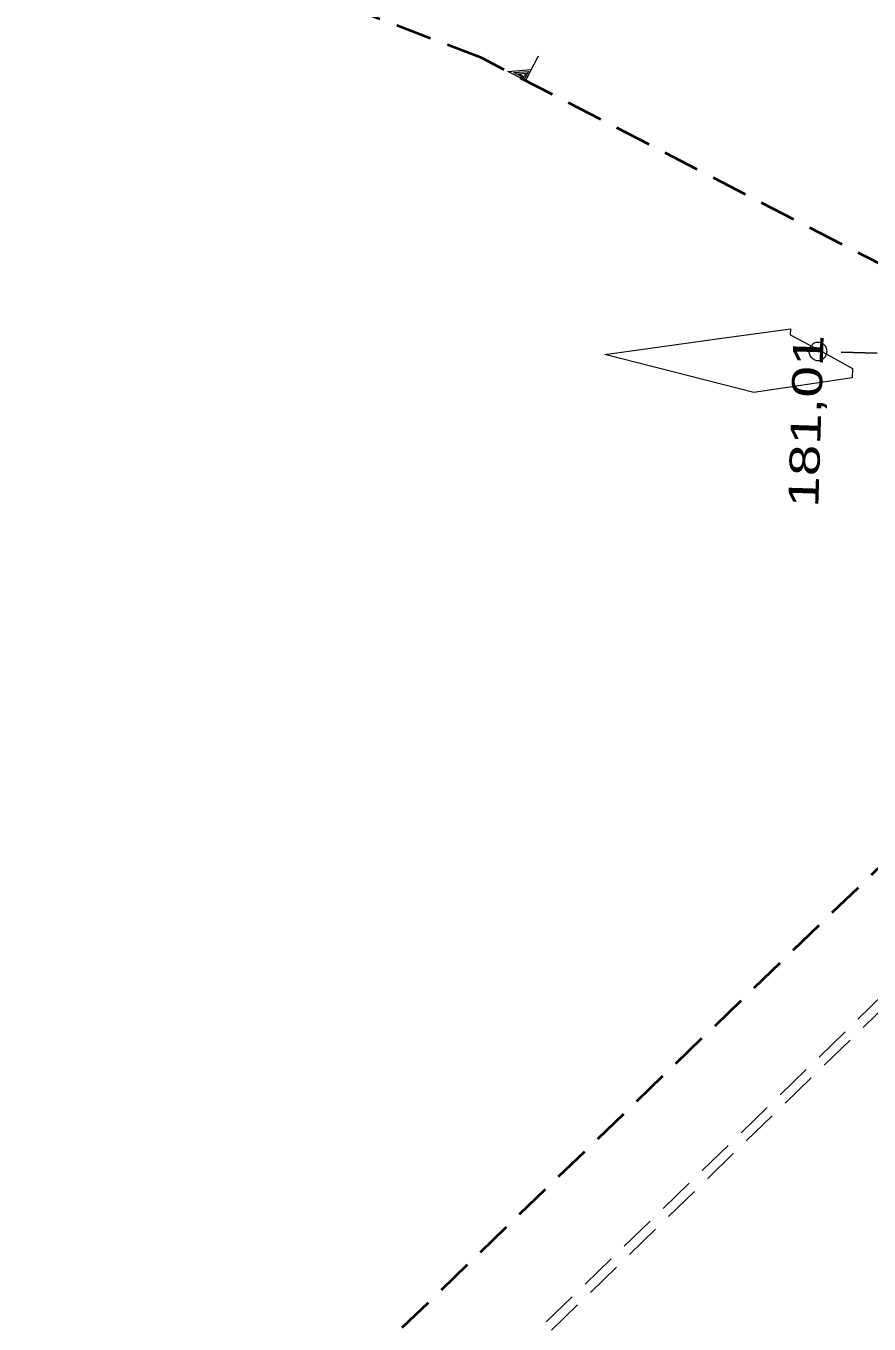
# Model space of a CAD drawing. Extents: x -740851 to -738888, y -1041382 to -1040235.
# Drawn here: x -739839.61 to -739811.68, y -1040534.07 to -1040491.06 of the extents above; entities that cross this region are included whole.
import ezdxf

# ---------------------------------------------------------------- set-up
doc = ezdxf.new("R2010")
doc.units = 0
doc.header["$LTSCALE"] = 0.4
doc.linetypes.add('MEDIUM_DASHED', pattern=[4.5, 3, -1.5])
for name, color, linetype, lineweight in [('18', 7, 'Continuous', 13), ('38', 7, 'Continuous', 13), ('39', 7, 'MEDIUM_DASHED', 13), ('8', 7, 'Continuous', 13)]:
    doc.layers.add(name, color=color, linetype=linetype, lineweight=lineweight)

msp = doc.modelspace()

# ---------------------------------------------------------------- linework, layer by layer
at = {"layer": '18', "linetype": 'MEDIUM_DASHED', "lineweight": 40}
msp.add_lwpolyline([(-739801.38, -1040504.08), (-739824.522, -1040492.113), (-739843.173, -1040485.007), (-739862.094, -1040478.655), (-739868.01, -1040476.84)], dxfattribs=at)
at = {"layer": '18'}
for points in [[(-739822.642, -1040492.053), (-739823.062, -1040492.865), (-739823.642, -1040492.566), (-739822.873, -1040492.499)], [(-739822.958, -1040492.558), (-739823.08, -1040492.795), (-739823.45, -1040492.603), (-739822.954, -1040492.56)], [(-739823.044, -1040492.621), (-739823.106, -1040492.74), (-739823.296, -1040492.642), (-739823.041, -1040492.624)]]:
    msp.add_lwpolyline(points, dxfattribs=at)
for points in [[(-739814.28, -1040501.09), (-739814.29, -1040501.29), (-739813.225, -1040501.849), (-739812.226, -1040502.402), (-739812.24, -1040502.71), (-739815.5, -1040503.2), (-739820.432, -1040501.939), (-739816.636, -1040501.415)], [(-739813.666, -1040501.883), (-739813.661, -1040501.913), (-739813.651, -1040501.942), (-739813.641, -1040501.97), (-739813.625, -1040501.998), (-739813.603, -1040502.025), (-739813.581, -1040502.046), (-739813.56, -1040502.067), (-739813.533, -1040502.087), (-739813.507, -1040502.102), (-739813.481, -1040502.116), (-739813.448, -1040502.129), (-739813.417, -1040502.137), (-739813.387, -1040502.138), (-739813.356, -1040502.14), (-739813.327, -1040502.136), (-739813.297, -1040502.131), (-739813.268, -1040502.121), (-739813.24, -1040502.111), (-739813.212, -1040502.095), (-739813.185, -1040502.073), (-739813.164, -1040502.051), (-739813.143, -1040502.03), (-739813.123, -1040502.003), (-739813.108, -1040501.977), (-739813.094, -1040501.951), (-739813.081, -1040501.918), (-739813.073, -1040501.887), (-739813.072, -1040501.857), (-739813.07, -1040501.826), (-739813.074, -1040501.797), (-739813.079, -1040501.767), (-739813.089, -1040501.738), (-739813.099, -1040501.71), (-739813.115, -1040501.682), (-739813.137, -1040501.655), (-739813.159, -1040501.634), (-739813.18, -1040501.613), (-739813.207, -1040501.593), (-739813.233, -1040501.578), (-739813.259, -1040501.564), (-739813.292, -1040501.551), (-739813.323, -1040501.543), (-739813.353, -1040501.542), (-739813.384, -1040501.54), (-739813.413, -1040501.544), (-739813.443, -1040501.549), (-739813.472, -1040501.559), (-739813.5, -1040501.569), (-739813.528, -1040501.585), (-739813.555, -1040501.607), (-739813.576, -1040501.629), (-739813.597, -1040501.65), (-739813.617, -1040501.677), (-739813.632, -1040501.703), (-739813.646, -1040501.729), (-739813.659, -1040501.762), (-739813.667, -1040501.793), (-739813.668, -1040501.823), (-739813.67, -1040501.854)]]:
    msp.add_lwpolyline(points, close=True, dxfattribs=at)
at = {"layer": '18', "linetype": 'MEDIUM_DASHED', "lineweight": 25}
msp.add_lwpolyline([(-739764.8, -1040509.34), (-739769.103, -1040507.543), (-739773.123, -1040506.414), (-739777.515, -1040505.303), (-739782.543, -1040504.403), (-739786.933, -1040503.786), (-739791.776, -1040503.067), (-739793.941, -1040502.746), (-739796.322, -1040502.462), (-739800.245, -1040502.273), (-739807.808, -1040502.015), (-739813.37, -1040501.84)], dxfattribs=at)
at = {"layer": '38', "linetype": 'MEDIUM_DASHED'}
msp.add_lwpolyline([(-739768.78, -1040522.16), (-739769.767, -1040523.416), (-739770.8, -1040525.186), (-739789.007, -1040514.675), (-739802.146, -1040514.35), (-739881.581, -1040591.514)], dxfattribs=at)
at = {"layer": '39'}
msp.add_lwpolyline([(-739768.78, -1040522.16), (-739770.749, -1040525.533), (-739789.095, -1040514.942), (-739801.973, -1040514.623), (-739881.335, -1040591.716)], dxfattribs=at)
at = {"layer": '8', "linetype": 'MEDIUM_DASHED', "lineweight": 40}
msp.add_lwpolyline([(-739884.124, -1040589.189), (-739802.643, -1040510.533), (-739800.406, -1040510.509)], dxfattribs=at)

# ---------------------------------------------------------------- texts
at = {"layer": '18', "width": 1.4}
msp.add_text('181,01', height=1, rotation=88.195, dxfattribs=at).set_placement((-739813.361, -1040507.024))

doc.saveas('drawing.dxf')
